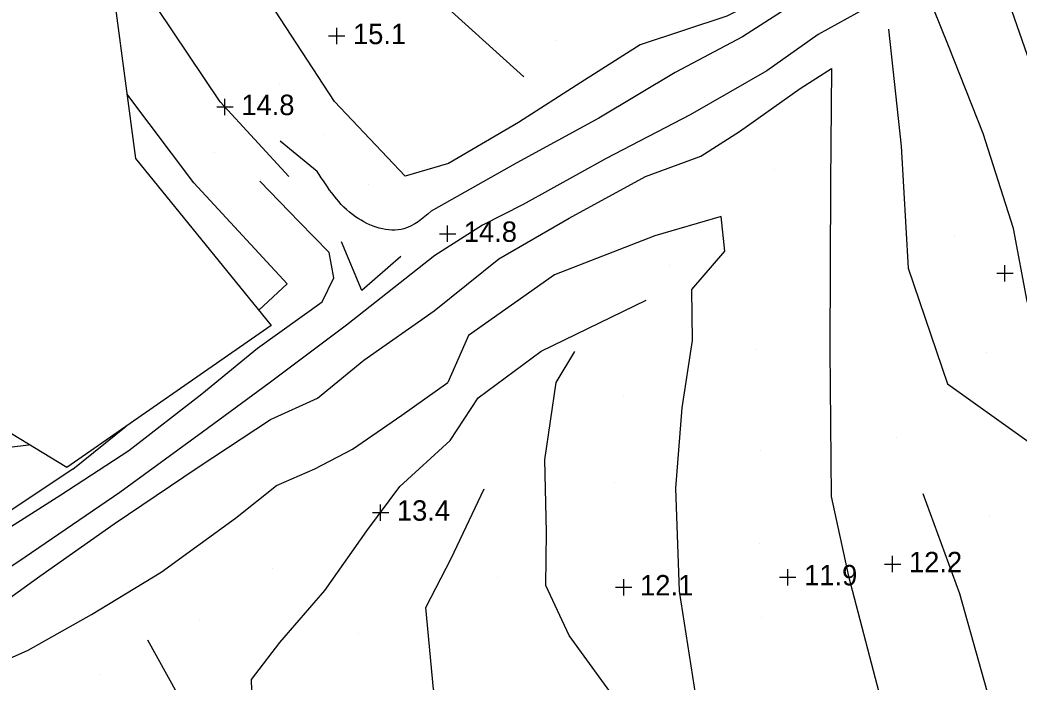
# Model space of a CAD drawing. Extents: x 2316231 to 2323598, y 363169 to 371906.
# Drawn here: x 2317584.1 to 2317829, y 369310.4 to 369472.6 of the extents above; entities that cross this region are included whole.
import ezdxf

# ---------------------------------------------------------------- set-up
doc = ezdxf.new("R2010")
doc.units = 0
for name, color, linetype in [('RD_DTM_BkLn1', 7, 'Continuous'), ('RD_DTM_Holes', 7, 'Continuous'), ('RD_DTM_Spot', 7, 'Continuous'), ('RD_DTM_Void', 7, 'Continuous'), ('RD_EX_Road', 7, 'Continuous')]:
    doc.layers.add(name, color=color, linetype=linetype)

msp = doc.modelspace()

# ---------------------------------------------------------------- linework, layer by layer
at = {"layer": 'RD_DTM_BkLn1'}
msp.add_line((2317597.03, 369362.555), (2317610.113, 369373.019), dxfattribs=at)
for points in [[(2317707.459, 369458.658), (2317685.564, 369478.537), (2317668.721, 369500.231), (2317652.105, 369520.766), (2317643.78, 369535.353), (2317631.185, 369559.556), (2317630.564, 369560.611)], [(2317774.381, 369482.149), (2317757.159, 369473.513), (2317735.967, 369466.484), (2317721.405, 369457.297), (2317706.207, 369447.488), (2317689.022, 369437.44), (2317678.45, 369434.297), (2317661.108, 369452.593), (2317643.932, 369479.04), (2317629.949, 369506.944), (2317613.739, 369535.541), (2317609.862, 369542.441)], [(2317649.912, 369434.222), (2317633.129, 369452.552), (2317613.788, 369481.434), (2317602.985, 369504.107), (2317590.106, 369525.102)], [(2317879.136, 369382.167), (2317874.25, 369410.948), (2317867.882, 369441.552), (2317861.781, 369466.246), (2317854.18, 369494.015), (2317846.841, 369492.251), (2317839.564, 369488.553), (2317849.214, 369453.217), (2317860.43, 369406.891), (2317860.46, 369376.38), (2317843.276, 369370.538), (2317835.563, 369388.353), (2317830.726, 369403.645), (2317827.43, 369421.496), (2317819.96, 369444.8), (2317811.467, 369466.26), (2317807.72, 369475.543), (2317824.396, 369482.366), (2317838.341, 369442.185)], [(2317796.758, 369470.36), (2317799.914, 369441.671), (2317801.618, 369411.736), (2317811.234, 369383.407), (2317832.949, 369367.93)], [(2317656.957, 369379.9), (2317668.306, 369389.246), (2317685.543, 369401.271), (2317701.358, 369414.056), (2317718.579, 369424.05), (2317737.238, 369434.26), (2317750.845, 369439.178), (2317760.298, 369445.214), (2317775.128, 369455.793), (2317782.837, 369460.705)], [(2317782.837, 369460.705), (2317782.594, 369432.642), (2317782.438, 369391.736), (2317782.714, 369355.792), (2317786.981, 369336.313), (2317794.399, 369307.852), (2317804.873, 369274.863), (2317815.931, 369232.668), (2317820.146, 369203.448), (2317820.711, 369190.542), (2317821.19, 369170.485), (2317822.084, 369161.146), (2317826.2, 369140.318), (2317830.794, 369114.952), (2317834.404, 369093.232), (2317825.488, 369075.338), (2317850.452, 369082.918), (2317873.473, 369090.997)], [(2317642.598, 369401.467), (2317649.533, 369407.965), (2317626.698, 369432.64), (2317610.299, 369454.447)], [(2317756.731, 369415.911), (2317755.821, 369424.441), (2317739.583, 369419.683), (2317714.974, 369410.112), (2317693.904, 369395.28), (2317688.85, 369383.75)], [(2317677.347, 369414.663), (2317667.778, 369406.266), (2317662.816, 369418.221)], [(2317760.77, 369252.893), (2317756.834, 369265.094), (2317753.065, 369283.07), (2317750.101, 369303.893), (2317745.612, 369332.635), (2317744.731, 369357.862), (2317746.292, 369377.559), (2317748.751, 369394.003), (2317748.589, 369406.502), (2317756.731, 369415.911)], [(2317696.262, 369379.988), (2317711.723, 369391.409), (2317737.468, 369403.9)], [(2317749.221, 369201.912), (2317744.215, 369210.449), (2317737.856, 369231.761), (2317736.551, 369248.681), (2317735.802, 369268.773), (2317735.11, 369288.248), (2317730.903, 369304.793), (2317718.557, 369321.756), (2317712.857, 369334.049), (2317713.043, 369347.119), (2317712.64, 369364.808), (2317715.43, 369383.715), (2317719.945, 369391.379)], [(2317574.537, 369313.015), (2317586.101, 369318.13), (2317601.582, 369326.904), (2317618.661, 369337.291), (2317636.89, 369350.491), (2317646.938, 369358.492), (2317656.276, 369362.602), (2317665.518, 369367.445), (2317677.624, 369375.78), (2317688.85, 369383.75)], [(2317603.388, 369234.989), (2317597.064, 369240.622), (2317586.563, 369255.484), (2317572.84, 369273.041), (2317557.863, 369287.639), (2317545.146, 369303.625), (2317558.121, 369313.62), (2317570.582, 369323.037), (2317588.942, 369336.266), (2317607.148, 369349.12), (2317627.756, 369363.021), (2317645.481, 369374.669), (2317656.957, 369379.9)], [(2317732.771, 369138.232), (2317731.078, 369144.425), (2317727.811, 369160.658), (2317724.628, 369173.086), (2317718.451, 369186.469), (2317708.67, 369199.452), (2317698.66, 369210.132), (2317690.619, 369225.079), (2317677.886, 369240.149), (2317666.024, 369251.417), (2317649.875, 369266.891), (2317644.354, 369280.88), (2317641.249, 369295.167), (2317640.768, 369310.985), (2317647.745, 369320.045), (2317658.722, 369332.777), (2317669.074, 369347.368), (2317677.092, 369358.284), (2317689.442, 369369.518), (2317696.262, 369379.988)], [(2317597.03, 369362.555), (2317577.683, 369349.661), (2317561.222, 369337.594), (2317550.428, 369329.852), (2317537.174, 369323.738), (2317531.533, 369323.113), (2317528.754, 369326.383), (2317535.899, 369330.618), (2317532.413, 369334.708), (2317523.035, 369333.417), (2317520.914, 369336.936), (2317540.742, 369348.312), (2317558.935, 369360.844), (2317572.16, 369366.779), (2317586.152, 369368.445), (2317586.329, 369368.548)], [(2317746.743, 369171.098), (2317740.844, 369182.992), (2317734.329, 369197.148), (2317729.589, 369206.155), (2317719.181, 369224.839), (2317708.439, 369246.95), (2317699.84, 369266.958), (2317691.105, 369290.222), (2317685.36, 369308.581), (2317683.507, 369328.587), (2317689.726, 369340.606), (2317697.767, 369357.685)], [(2317805.22, 369356.593), (2317814.174, 369332.04), (2317822.189, 369303.576), (2317827.399, 369286.514), (2317834.918, 369268.068), (2317842.317, 369242.711), (2317843.668, 369215.87), (2317847.498, 369190.663), (2317847.31, 369179.873), (2317846.989, 369166.565), (2317849.65, 369145.96), (2317853.827, 369120.823), (2317855.756, 369092.761)], [(2317615.349, 369320.71), (2317622.538, 369307.684), (2317626.274, 369287.565), (2317628.005, 369277.192), (2317637.437, 369264.981)]]:
    msp.add_lwpolyline(points, dxfattribs=at)
at = {"layer": 'RD_DTM_Holes'}
msp.add_lwpolyline([(2317552.224, 369499.945), (2317569.13, 369479.982), (2317604.93, 369494.562), (2317612.413, 369438.655), (2317645.651, 369397.707), (2317595.579, 369362.923), (2317530.433, 369402.545), (2317549.595, 369445.469), (2317512.951, 369476.874), (2317552.224, 369499.945)], dxfattribs=at)
at = {"layer": 'RD_DTM_Spot'}
for p, q in [((2317715.182, 369467.461), (2317715.182, 369467.461)), ((2317647.543, 369456.943), (2317647.543, 369456.943)), ((2317658.604, 369444.534), (2317658.604, 369444.534)), ((2317631.703, 369440.174), (2317631.703, 369440.174)), ((2317768.854, 369435.865), (2317768.854, 369435.865)), ((2317669.464, 369432.387), (2317669.464, 369432.387)), ((2317812.977, 369419.889), (2317812.977, 369419.889)), ((2317743.124, 369412.493), (2317743.124, 369412.493)), ((2317764.106, 369391.755), (2317764.106, 369391.755)), ((2317820.811, 369391.02), (2317820.811, 369391.02)), ((2317731.846, 369380.35), (2317731.846, 369380.35)), ((2317798.762, 369370.235), (2317798.762, 369370.235)), ((2317765.442, 369367.104), (2317765.442, 369367.104)), ((2317729.587, 369359.189), (2317729.587, 369359.189)), ((2317821.568, 369351.183), (2317821.568, 369351.183)), ((2317765.25, 369344.326), (2317765.25, 369344.326)), ((2317645.899, 369338.147), (2317645.899, 369338.147)), ((2317700.916, 369335.976), (2317700.916, 369335.976)), ((2317731.976, 369333.705), (2317731.976, 369333.705)), ((2317765.565, 369326.122), (2317765.565, 369326.122)), ((2317627.979, 369325.636), (2317627.979, 369325.636)), ((2317667.063, 369322.159), (2317667.063, 369322.159)), ((2317603.89, 369312.267), (2317603.89, 369312.267))]:
    msp.add_line(p, q, dxfattribs=at)
at = {"layer": 'RD_DTM_Void'}
for p, q in [((2317661.652, 369466.658), (2317661.652, 369470.658)), ((2317659.652, 369468.658), (2317663.652, 369468.658)), ((2317634.304, 369449.269), (2317634.304, 369453.269)), ((2317632.304, 369451.269), (2317636.304, 369451.269)), ((2317688.795, 369418.209), (2317688.795, 369422.209)), ((2317686.795, 369420.209), (2317690.795, 369420.209)), ((2317825.283, 369408.538), (2317825.283, 369412.538)), ((2317823.283, 369410.538), (2317827.283, 369410.538)), ((2317672.4, 369349.895), (2317672.4, 369353.895)), ((2317670.4, 369351.895), (2317674.4, 369351.895)), ((2317797.8, 369337.252), (2317797.8, 369341.252)), ((2317795.8, 369339.252), (2317799.8, 369339.252)), ((2317770.119, 369336.047), (2317774.119, 369336.047)), ((2317772.119, 369334.047), (2317772.119, 369338.047)), ((2317729.944, 369333.585), (2317733.944, 369333.585)), ((2317731.944, 369331.585), (2317731.944, 369335.585))]:
    msp.add_line(p, q, dxfattribs=at)
at = {"layer": 'RD_EX_Road'}
msp.add_line((2317656.916, 369435.478), (2317647.778, 369442.907), dxfattribs=at)
for points in [[(2317847.653, 369501.391), (2317838.147, 369498.277), (2317823.659, 369492.003), (2317809.034, 369484.763), (2317796.155, 369478.218), (2317779.527, 369469.054)], [(2317770.807, 369474.758), (2317761.026, 369468.468), (2317744.55, 369459.717), (2317725.831, 369448.517), (2317705.768, 369437.541), (2317684.818, 369425.755)], [(2317779.527, 369469.054), (2317766.961, 369460.109), (2317748.247, 369449.325), (2317727.622, 369438.629), (2317707.314, 369427.329), (2317697.38, 369422.316), (2317685.717, 369414.871)], [(2317533.634, 369317.797), (2317552.974, 369329.168), (2317573.601, 369343.213), (2317594.111, 369356.207), (2317610.732, 369367.067), (2317628.627, 369381.005), (2317642.253, 369392.129), (2317658.096, 369403.496), (2317660.946, 369409.437), (2317659.78, 369415.583), (2317652.45, 369423.12), (2317642.847, 369433.052)], [(2317685.717, 369414.871), (2317664.066, 369397.768), (2317645.087, 369383.566), (2317628.79, 369371.564), (2317608.521, 369356.806), (2317585.375, 369340.959), (2317570.124, 369330.707), (2317553.94, 369320.243), (2317544.872, 369315.893), (2317538.788, 369311.243)]]:
    msp.add_lwpolyline(points, dxfattribs=at)
msp.add_spline([(2317684.818, 369425.755), (2317678.121, 369421.404), (2317666.275, 369424.356), (2317656.916, 369435.478)], degree=3, dxfattribs=at)

# ---------------------------------------------------------------- texts
at = {"layer": 'RD_DTM_Void'}
for s, p in [('15.1', (2317665.652, 369466.658)), ('14.8', (2317638.304, 369449.269)), ('14.8', (2317692.795, 369418.209)), ('13.4', (2317676.4, 369349.895)), ('12.2', (2317801.8, 369337.252)), ('11.9', (2317776.119, 369334.047)), ('12.1', (2317735.944, 369331.585))]:
    msp.add_text(s, height=5, dxfattribs=at).set_placement(p)

doc.saveas('drawing.dxf')
